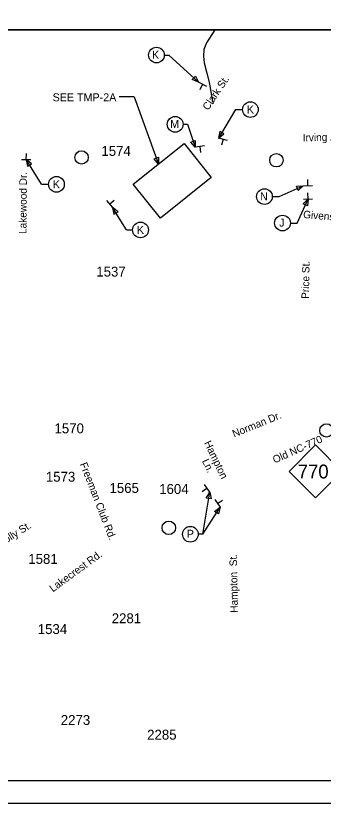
# Model space of a CAD drawing. Extents: x 2157572 to 5059327, y 715220 to 1674494.
# Drawn here: x 2163670 to 2166357, y 722289 to 729165 of the extents above; entities that cross this region are included whole.
import ezdxf

# ---------------------------------------------------------------- set-up
doc = ezdxf.new("R2010")
doc.units = 0
for name, color, linetype in [('Exist Cultural Church Label', 7, 'Continuous'), ('Exist Cultural Recreational Athletic Track', 7, 'Continuous'), ('Exist Road Primary US Shield CELL', 7, 'Continuous'), ('Exist Road Primary US Structure Standard Bridge Number Label', 7, 'Continuous'), ('Exist Road Secondary Type 10 SR Number Label', 7, 'Continuous'), ('Exist Road Secondary Type 51 Divided Label', 7, 'Continuous'), ('Exist Road Secondary Type 51 Undivided 3 Lane Attributed', 7, 'Continuous'), ('Level 51', 7, 'Continuous'), ('Level 53', 7, 'Continuous'), ('Map Preparation County Base Legend Highway Garage or Maintenance Office', 7, 'Continuous'), ('Map Preparation County Base Legend Monument Small Historical Site', 7, 'Continuous'), ('Map Preparation County Base Legend Weight Station', 7, 'Continuous'), ('Map Preparation County North Arrow Shadow', 7, 'Continuous'), ('Map Preparation County North Arrow White Shapes', 7, 'Continuous')]:
    doc.layers.add(name, color=color, linetype=linetype)

msp = doc.modelspace()

# ---------------------------------------------------------------- linework, layer by layer
at = {"layer": 'Exist Cultural Church Label'}
for centre in [(2164899.4, 728821.1), (2165720.3, 728345.2), (2165063, 728216.6), (2164025.6, 727692.8), (2165843.2, 727585.5), (2166000.9, 727354.6), (2164759.9, 727294.3), (2165195.7, 724637.6)]:
    msp.add_circle(centre, 68.6, dxfattribs=at)
at = {"layer": 'Exist Road Primary US Structure Standard Bridge Number Label'}
msp.add_lwpolyline([(2164695.7, 727692.7), (2165140.7, 728049.4), (2165378.5, 727752.7), (2164933.5, 727396)], close=True, dxfattribs=at)
at = {"layer": 'Exist Road Secondary Type 10 SR Number Label'}
msp.add_lwpolyline([(2165408.9, 729042.7), (2165336.4, 728927), (2165314.5, 728870.2), (2165309.6, 728811.1), (2165313, 728783.3), (2165316.5, 728754.7), (2165330.5, 728697.6), (2165331.5, 728694.2), (2165344.9, 728641.7), (2165359.9, 728582.9), (2165372.2, 728521.3), (2165378.4, 728482.3), (2165381.5, 728462.5), (2165387.6, 728429.3), (2165391.1, 728412.7), (2165394.2, 728398)], dxfattribs=at)
at = {"layer": 'Exist Road Secondary Type 51 Divided Label'}
msp.add_lwpolyline([(2157571.9, 722288.7), (2171075.9, 722288.7), (2171075.9, 731088.6), (2157571.9, 731088.6)], close=True, dxfattribs=at)
at = {"layer": 'Exist Road Secondary Type 51 Undivided 3 Lane Attributed'}
msp.add_lwpolyline([(2170485.5, 727897.1), (2170495.8, 729042.7), (2158875.9, 729042.7), (2158875.9, 722488.7), (2166434.4, 722488.7), (2166434.4, 723622.8), (2170875.9, 723622.8), (2170875.9, 727897.1)], close=True, dxfattribs=at)
at = {"layer": 'Level 51'}
for p, q in [((2164968, 728821.1), (2165007.6, 728821.1)), ((2165007.6, 728821.1), (2165267, 728584)), ((2164705.8, 728457), (2164574.1, 728457)), ((2164705.8, 728457), (2164916.8, 727870)), ((2165589.4, 728345.2), (2165442.1, 728095.5)), ((2165589.4, 728345.2), (2165651.7, 728345.2)), ((2165131.6, 728216.6), (2165171.2, 728216.6)), ((2165171.2, 728216.6), (2165238.1, 728016.5)), ((2163894.7, 727692.8), (2163761.6, 727908.7)), ((2163894.7, 727692.8), (2163957, 727692.8)), ((2165970.8, 727585.5), (2166181.6, 727680.7)), ((2165911.8, 727585.5), (2165970.8, 727585.5)), ((2166128.5, 727354.6), (2166224.2, 727565.2)), ((2164637.3, 727294.3), (2164516.6, 727490.2)), ((2166069.5, 727354.6), (2166128.5, 727354.6)), ((2164637.3, 727294.3), (2164691.3, 727294.3)), ((2165304, 724637.6), (2165364.8, 725004.9)), ((2165304, 724637.6), (2165455.8, 724872.9)), ((2165304, 724637.6), (2165264.4, 724637.6))]:
    msp.add_line(p, q, dxfattribs=at)
for points in [[(2165211.6, 728606.5), (2165239.6, 728637.2), (2165267, 728584)], [(2165488.4, 728133.3), (2165452.7, 728154.4), (2165442.1, 728095.5)], [(2165199.5, 728061.8), (2165238.5, 728076), (2165238.1, 728016.2)], [(2163773.4, 727850.1), (2163808.7, 727871.9), (2163761.6, 727908.7)], [(2164878.3, 727915.7), (2164917.4, 727929.7), (2164916.8, 727870)], [(2166139, 727638.7), (2166122, 727676.5), (2166181.6, 727680.7)], [(2166219.9, 727505.6), (2166182.1, 727522.8), (2166224.2, 727565.2)], [(2164528.3, 727431.6), (2164563.6, 727453.3), (2164516.6, 727490.2)], [(2165376.1, 724946.2), (2165335.2, 724953), (2165364.8, 725004.9)], [(2165442.9, 724814.5), (2165408, 724837), (2165455.8, 724872.9)]]:
    msp.add_lwpolyline(points, close=True, dxfattribs=at)
for centre in [(2164245.1, 727927.1), (2165947.6, 727902.8), (2166385, 725543.6), (2165007.6, 724693.2)]:
    msp.add_circle(centre, 58.7, dxfattribs=at)
at = {"layer": 'Map Preparation County Base Legend Highway Garage or Maintenance Office'}
for centre in [(2164899.4, 728821.1), (2165720.3, 728345.2), (2165063, 728216.6), (2164025.6, 727692.8), (2165843.2, 727585.5), (2166000.9, 727354.6), (2164759.9, 727294.3), (2165195.7, 724637.6)]:
    msp.add_circle(centre, 68.6, dxfattribs=at)
at = {"layer": 'Map Preparation County Base Legend Monument Small Historical Site'}
msp.add_lwpolyline([(2166058.5, 725186.7), (2166288.7, 725416.9), (2166518.9, 725186.7), (2166288.7, 724956.4)], close=True, dxfattribs=at)
at = {"layer": 'Map Preparation County North Arrow Shadow'}
for p, q in [((2165339, 728547.1), (2165267, 728584)), ((2165302.7, 728565.7), (2165278.7, 728519)), ((2165520.7, 728076.3), (2165442.1, 728095.5)), ((2165481.1, 728086), (2165468.6, 728035)), ((2165318.4, 728027.9), (2165238.3, 728016.1)), ((2165278, 728021.9), (2165285.7, 727970)), ((2163761.6, 727908.7), (2163762.6, 727961.2)), ((2163720.8, 727909.5), (2163801.8, 727908)), ((2166181.6, 727680.7), (2166262.6, 727682.6)), ((2166222.4, 727681.7), (2166221.2, 727734.1)), ((2166224.2, 727565.2), (2166222.9, 727617.7)), ((2164464.3, 727552), (2164516.6, 727490.2)), ((2164490.7, 727520.9), (2164530.8, 727554.7)), ((2166183.3, 727564.3), (2166264.3, 727566.2)), ((2165364.8, 725004.9), (2165318.9, 725071.6)), ((2165341.7, 725038.5), (2165298.4, 725008.7)), ((2165409.9, 724939.6), (2165455.8, 724872.9)), ((2165433, 724906), (2165476.2, 724935.7))]:
    msp.add_line(p, q, dxfattribs=at)
at = {"layer": 'Map Preparation County North Arrow White Shapes'}
msp.add_line((2158905.6, 729042.7), (2170875.9, 729042.7), dxfattribs=at)
msp.add_lwpolyline([(2170875.9, 730888.7), (2158875.9, 730888.7), (2158875.9, 722488.7), (2170875.9, 722488.7)], close=True, dxfattribs=at)

# ---------------------------------------------------------------- texts
at = {"layer": 'Exist Cultural Recreational Athletic Track'}
for s, height, rotation, p in [('Clark St.', 65.68, 56.26085, (2165351.4, 728333.3)), ('Irving Ave.', 65.681, 1.54503, (2166178.4, 728067.1)), ('Givens St.', 65.68, 355.06529, (2166179.3, 727398.8)), ('Price St.', 65.68, 89.02561, (2166232, 726692)), ('Norman Dr.', 65.68, 22.21598, (2165578.3, 725481.4)), ('Hampton ', 65.68, 295.61569, (2165313.8, 725434.9)), ('Ln.', 65.68, 295.61569, (2165296, 725277)), ('Holly St.', 65.68, 31.87305, (2163534.5, 724524.5)), ('Hampton  St.', 65.681, 91.06312, (2165611.4, 723953))]:
    msp.add_text(s, height=height, rotation=rotation, dxfattribs=at).set_placement(p)
at = {"layer": 'Exist Road Primary US Shield CELL'}
for s, height, rotation, p in [('Lakewood Dr.', 65.681, 89.51155, (2163763, 727259)), ('Old NC-770', 65.68, 24.13273, (2165933, 725254.4)), ('Freeman Club Rd.', 65.681, 291.27229, (2164229, 725250)), ('Lakecrest Rd.', 65.681, 36.15855, (2163993.9, 724128.8))]:
    msp.add_text(s, height=height, rotation=rotation, dxfattribs=at).set_placement(p)
at = {"layer": 'Exist Road Primary US Structure Standard Bridge Number Label'}
for s, height, p in [('K', 70, (2164860.3, 728789)), ('SEE TMP-2A', 70.03, (2163991.9, 728417.1)), ('K', 70, (2165688.5, 728310.9)), ('M', 70, (2165019.4, 728184.6)), ('K', 70, (2163993.8, 727658.4)), ('N', 70, (2165804.2, 727554.1)), ('K', 70, (2164728.1, 727259.9)), ('J', 70, (2165972.5, 727323.2)), ('P', 70, (2165165, 724606.2))]:
    msp.add_text(s, height=height, dxfattribs=at).set_placement(p)
at = {"layer": 'Level 53'}
for s, p in [('1574', (2164418.4, 727941.2)), ('1537', (2164373.8, 726887.5)), ('1570', (2164008.5, 725518.9)), ('1573', (2163932.9, 725096)), ('1565', (2164489, 724998.2)), ('1604', (2164923.2, 724989.3)), ('1581', (2163779.3, 724378.7)), ('2281', (2164508.5, 723860.4)), ('1534', (2163862.2, 723765.9)), ('2273', (2164063.4, 722972.5)), ('2285', (2164818.1, 722844.3))]:
    msp.add_text(s, height=86.42, dxfattribs=at).set_placement(p)
at = {"layer": 'Map Preparation County Base Legend Weight Station'}
msp.add_text('770', height=120.99, dxfattribs=at).set_placement((2166133.9, 725124.7))

doc.saveas('drawing.dxf')
